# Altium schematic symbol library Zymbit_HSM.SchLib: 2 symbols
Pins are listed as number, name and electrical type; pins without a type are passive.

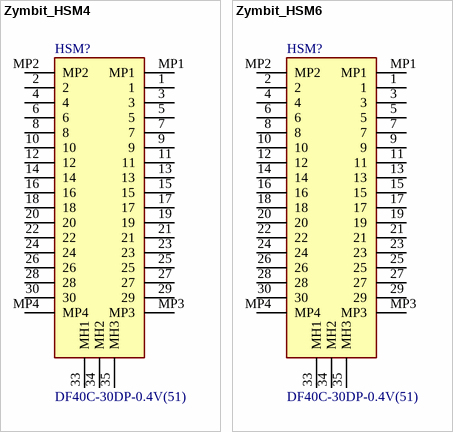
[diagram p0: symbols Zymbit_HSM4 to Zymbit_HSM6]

## Zymbit_HSM4
designator HSM?, comment DF40C-30DP-0.4V(51)
Connector,  30 Position Plug, Outer Shroud Contacts Surface Mount Gold; Manufacturer: HRS(Hirose)
footprint Zymbit_HSM4
pins: 1, 2, 3, 4, 5, 6, 7, 8, 9, 10, 11, 12, 13, 14, 15, 16, 17, 18, 19, 20, 21, 22, 23, 24, 25, 26, 27, 28, 29, 30, 33 MH1, 34 MH2, 35 MH3, MP1, MP2, MP3, MP4

## Zymbit_HSM6
designator HSM?, comment DF40C-30DP-0.4V(51)
Connector,  30 Position Plug, Outer Shroud Contacts Surface Mount Gold; Manufacturer: HRS(Hirose)
footprint Zymbit_HSM6
pins: 1, 2, 3, 4, 5, 6, 7, 8, 9, 10, 11, 12, 13, 14, 15, 16, 17, 18, 19, 20, 21, 22, 23, 24, 25, 26, 27, 28, 29, 30, 33 MH1, 34 MH2, 35 MH3, MP1, MP2, MP3, MP4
